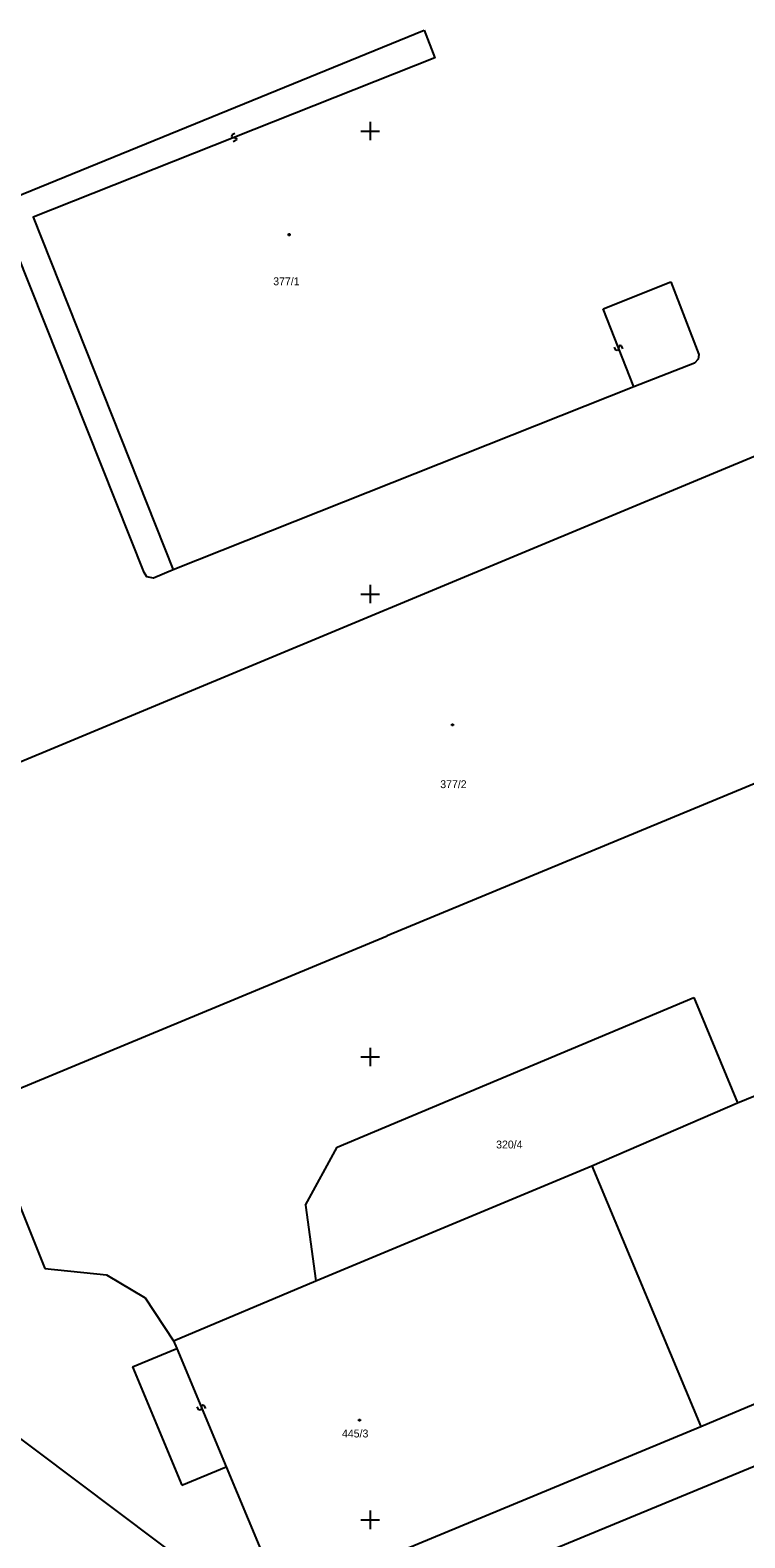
# Model space of a CAD drawing. Extents: x -492379 to -491966, y -1126153 to -1125860.
# Drawn here: x -492142 to -492095.7, y -1125961.2 to -1125863.5 of the extents above; entities that cross this region are included whole.
import ezdxf

# ---------------------------------------------------------------- set-up
doc = ezdxf.new("R2010")
doc.units = 0
doc.layers.add('katastrální mapa', color=7, linetype='Continuous')
doc.layers.add('síť', color=7, linetype='Continuous')

msp = doc.modelspace()

# ---------------------------------------------------------------- linework, layer by layer
at = {"layer": 'katastrální mapa'}
for p, q in [((-492143.53, -1125874.5), (-492116.5, -1125863.46)), ((-492128.95, -1125870.25), (-492128.98, -1125870.33)), ((-492128.98, -1125870.33), (-492128.96, -1125870.39)), ((-492128.76, -1125870.15), (-492128.95, -1125870.25)), ((-492128.96, -1125870.39), (-492128.88, -1125870.42)), ((-492128.88, -1125870.42), (-492128.75, -1125870.43)), ((-492128.68, -1125870.6), (-492128.87, -1125870.7)), ((-492128.75, -1125870.43), (-492128.67, -1125870.46)), ((-492128.65, -1125870.52), (-492128.68, -1125870.6)), ((-492128.67, -1125870.46), (-492128.65, -1125870.52)), ((-492125.3, -1125876.67), (-492125.21, -1125876.67)), ((-492125.3, -1125876.76), (-492125.3, -1125876.67)), ((-492125.21, -1125876.76), (-492125.3, -1125876.76)), ((-492125.21, -1125876.67), (-492125.21, -1125876.76)), ((-492104.9, -1125881.53), (-492100.52, -1125879.77)), ((-492102.91, -1125886.58), (-492104.9, -1125881.53)), ((-492104.08, -1125884.19), (-492104.18, -1125884)), ((-492103.9, -1125883.99), (-492103.91, -1125884.12)), ((-492103.87, -1125883.91), (-492103.9, -1125883.99)), ((-492103.81, -1125883.89), (-492103.87, -1125883.91)), ((-492103.73, -1125883.92), (-492103.81, -1125883.89)), ((-492103.63, -1125884.11), (-492103.73, -1125883.92)), ((-492104, -1125884.22), (-492104.08, -1125884.19)), ((-492103.94, -1125884.2), (-492104, -1125884.22)), ((-492103.91, -1125884.12), (-492103.94, -1125884.2)), ((-492102.91, -1125886.58), (-492132.76, -1125898.44)), ((-492150.75, -1125914.23), (-492091.06, -1125889.38)), ((-492083.52, -1125907.5), (-492118.89, -1125922.15)), ((-492114.71, -1125908.44), (-492114.62, -1125908.44)), ((-492114.71, -1125908.53), (-492114.71, -1125908.44)), ((-492114.62, -1125908.44), (-492114.62, -1125908.53)), ((-492114.62, -1125908.53), (-492114.71, -1125908.53)), ((-492145.34, -1125933.14), (-492118.89, -1125922.15)), ((-492122.14, -1125935.85), (-492099.03, -1125926.15)), ((-492099.03, -1125926.15), (-492096.2, -1125932.98)), ((-492096.2, -1125932.98), (-492092.51, -1125931.47)), ((-492145.34, -1125933.14), (-492141.08, -1125943.7)), ((-492105.64, -1125937.05), (-492096.2, -1125932.98)), ((-492098.58, -1125953.94), (-492054.42, -1125935.46)), ((-492124.18, -1125939.61), (-492122.14, -1125935.85)), ((-492123.52, -1125944.51), (-492105.64, -1125937.05)), ((-492105.64, -1125937.05), (-492098.58, -1125953.94)), ((-492124.18, -1125939.61), (-492123.52, -1125944.51)), ((-492119.27, -1125966.48), (-492056.7, -1125940.64)), ((-492141.08, -1125943.7), (-492137.08, -1125944.11)), ((-492137.08, -1125944.11), (-492134.57, -1125945.61)), ((-492132.74, -1125948.39), (-492123.52, -1125944.51)), ((-492134.57, -1125945.61), (-492132.74, -1125948.39)), ((-492152.49, -1125947.37), (-492127.23, -1125966.34)), ((-492132.74, -1125948.39), (-492132.53, -1125948.9)), ((-492135.39, -1125950.09), (-492132.53, -1125948.9)), ((-492132.53, -1125948.9), (-492129.33, -1125956.56)), ((-492135.39, -1125950.09), (-492132.19, -1125957.75)), ((-492131.1, -1125952.87), (-492131.21, -1125952.68)), ((-492131.02, -1125952.9), (-492131.1, -1125952.87)), ((-492130.97, -1125952.88), (-492131.02, -1125952.9)), ((-492130.93, -1125952.8), (-492130.97, -1125952.88)), ((-492130.89, -1125952.58), (-492130.93, -1125952.66)), ((-492130.93, -1125952.66), (-492130.93, -1125952.8)), ((-492130.84, -1125952.56), (-492130.89, -1125952.58)), ((-492130.76, -1125952.59), (-492130.84, -1125952.56)), ((-492130.65, -1125952.78), (-492130.76, -1125952.59)), ((-492124.3, -1125964.61), (-492098.58, -1125953.94)), ((-492120.735, -1125953.488), (-492120.645, -1125953.488)), ((-492120.735, -1125953.578), (-492120.735, -1125953.488)), ((-492120.645, -1125953.578), (-492120.735, -1125953.578)), ((-492120.645, -1125953.488), (-492120.645, -1125953.578)), ((-492132.19, -1125957.75), (-492129.33, -1125956.56)), ((-492129.33, -1125956.56), (-492125.72, -1125965.2))]:
    msp.add_line(p, q, dxfattribs=at)
for points in [[(-492116.5, -1125863.46), (-492115.81, -1125865.26), (-492141.82, -1125875.59), (-492132.76, -1125898.44)], [(-492132.76, -1125898.44), (-492134.04, -1125898.97), (-492134.47, -1125898.88), (-492134.65, -1125898.6), (-492143.83, -1125875.5), (-492143.83, -1125874.84), (-492143.53, -1125874.5)], [(-492100.52, -1125879.77), (-492098.7, -1125884.48), (-492098.75, -1125884.79), (-492098.98, -1125885.03), (-492102.91, -1125886.58)]]:
    msp.add_lwpolyline(points, dxfattribs=at)
at = {"layer": 'síť'}
for p, q in [((-492120.6, -1125870), (-492119.4, -1125870)), ((-492120, -1125869.4), (-492120, -1125870.6)), ((-492120, -1125899.4), (-492120, -1125900.6)), ((-492120.6, -1125900), (-492119.4, -1125900)), ((-492120, -1125929.4), (-492120, -1125930.6)), ((-492120.6, -1125930), (-492119.4, -1125930)), ((-492120.6, -1125960), (-492119.4, -1125960)), ((-492120, -1125959.4), (-492120, -1125960.6))]:
    msp.add_line(p, q, dxfattribs=at)

# ---------------------------------------------------------------- texts
at = {"layer": 'katastrální mapa'}
for s, p in [('377/1', (-492126.28, -1125879.99)), ('377/2', (-492115.46, -1125912.58)), ('320/4', (-492111.84, -1125935.93)), ('445/3', (-492121.825, -1125954.658))]:
    msp.add_text(s, height=0.51, dxfattribs=at).set_placement(p)

doc.saveas('drawing.dxf')
